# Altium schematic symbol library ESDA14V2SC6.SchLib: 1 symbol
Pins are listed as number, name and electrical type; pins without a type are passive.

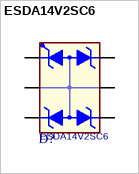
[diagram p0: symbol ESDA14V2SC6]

## ESDA14V2SC6
designator D?
footprint ST_SOT23-6L
pins: 1, 2, 3, 4, 5, 6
